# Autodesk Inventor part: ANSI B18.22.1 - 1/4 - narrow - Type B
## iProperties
Comments: To add or edit properties for Autodesk Inventor files, use iProperties.
Created: 2005-06
Part Number: ANSI B18.22.1 - 1/4 - narrow - Type B
Vendor: Autodesk Inc.
Document SubType Name: Modeling
Designer: John Blackburn
Material: Default
Description: Washer B
Standard: ANSI B18.22.1
Alert: To add or edit properties for Autodesk Inventor files, use iProperties.
Control State: 0
Master: False
Checked Out: False
Shininess: 64.0
Length Units: 11272
Angle Units: 11279
Time Units: 11290
Mass Units: 11286
Length Display Precision: 3
Angle Display Precision: 2
Compacted: True
Classification: un/spsc 31161807
Density: 0.0
Volumn: 0.0
Area: 0.0
PropertySet Name: Model Information
Author: John Blackburn
Revision Number: 8
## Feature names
1. Body [Extrusion]
